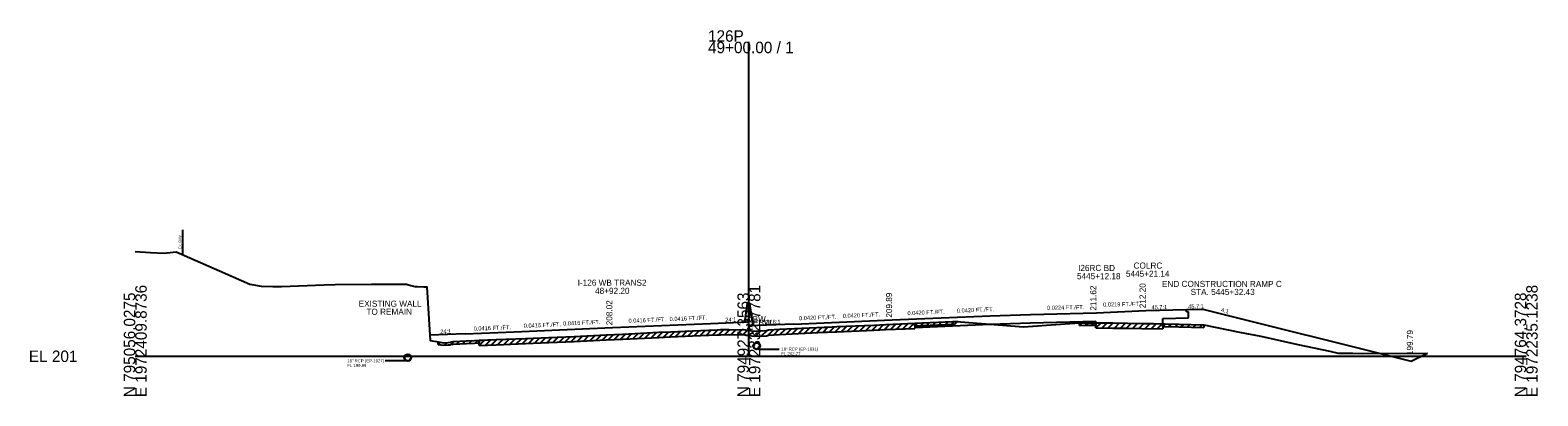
# Model space of a CAD drawing. Extents: x -161 to 1970889, y -4362 to 797231.
# Drawn here: x 1974.3 to 2342.8, y 1490.3 to 1579.8 of the extents above; entities that cross this region are included whole.
import ezdxf

# ---------------------------------------------------------------- set-up
doc = ezdxf.new("R2010")
doc.units = 0
for name, color, linetype in [('RD_GPK_XS_Cell', 7, 'Continuous'), ('RD_XS_Base', 7, 'Continuous'), ('RD_XS_EarthShd', 7, 'Continuous'), ('RD_XS_ExGround', 7, 'Continuous'), ('RD_XS_ExPaveRet', 7, 'Continuous'), ('RD_XS_ExRW', 7, 'Continuous'), ('RD_XS_MedBWall', 7, 'Continuous'), ('RD_XS_Misc_Line', 7, 'Continuous'), ('RD_XS_Pave', 7, 'Continuous'), ('RD_XS_PaveOvlay', 7, 'Continuous'), ('RD_XS_PaveShd', 7, 'Continuous'), ('RD_XS_Pipe', 7, 'Continuous'), ('RD_XS_TieSlope', 7, 'Continuous'), ('RD_XS_TX_Elev_EX', 7, 'Continuous'), ('RD_XS_TX_Elev_PR', 7, 'Continuous'), ('RD_XS_TX_Misc', 7, 'Continuous'), ('RD_XS_TX_MkPT', 7, 'Continuous'), ('RD_XS_TX_Notes', 7, 'Continuous'), ('RD_XS_TX_Profile', 7, 'Continuous'), ('RD_XS_TX_ShdSlope', 7, 'Continuous'), ('RD_XS_TX_Slope', 7, 'Continuous'), ('RD_XS_TX_Station', 7, 'Continuous')]:
    doc.layers.add(name, color=color, linetype=linetype)

msp = doc.modelspace()

# ---------------------------------------------------------------- linework, layer by layer
at = {"layer": 'RD_GPK_XS_Cell'}
for p, q in [((2150, 1500), (2150, 1576.99)), ((2000, 1500), (2150, 1500)), ((2150, 1500), (2340, 1500))]:
    msp.add_line(p, q, dxfattribs=at)
at = {"layer": 'RD_XS_Base'}
for p, q in [((2256.97, 1510.86), (2256.97, 1511.42)), ((2190.52, 1507.08), (2209, 1507.86)), ((2209, 1507.86), (2218.86, 1508.22)), ((2218.86, 1508.22), (2234.82, 1508.58)), ((2251.16, 1509.25), (2257.47, 1509.39)), ((2257.47, 1510.87), (2256.97, 1510.86)), ((2257.47, 1509.39), (2257.47, 1510.87))]:
    msp.add_line(p, q, dxfattribs=at)
at = {"layer": 'RD_XS_EarthShd'}
msp.add_line((2256.97, 1511.42), (2260.98, 1511.51), dxfattribs=at)
at = {"layer": 'RD_XS_ExGround'}
for points in [[(2000, 1525.66), (2003.69, 1525.44), (2007.1, 1525.22), (2007.77, 1525.34), (2009.96, 1525.6), (2023.96, 1519.48), (2028.04, 1517.66), (2028.52, 1517.56), (2030.78, 1517.2), (2033.6, 1517.11), (2034.53, 1517.05), (2035.75, 1517.1), (2046.16, 1517.52), (2048.89, 1517.58), (2057.72, 1517.68), (2062.21, 1517.65), (2063.99, 1517.63), (2065.81, 1517.62), (2066.29, 1517.62), (2067.38, 1517.35), (2068.3, 1517.08), (2068.94, 1517.07), (2070.5, 1517.01), (2071.26, 1517.01), (2072.05, 1503.87), (2072.6, 1503.77), (2073.66, 1503.61), (2075.35, 1503.33), (2076.51, 1503.4), (2077.09, 1503.43), (2077.33, 1503.55), (2077.58, 1503.54), (2077.69, 1503.61), (2080.99, 1503.76), (2082.93, 1503.86), (2088.21, 1504.07), (2095.41, 1504.35), (2101.05, 1504.6), (2107.31, 1504.88), (2115.1, 1505.24), (2119.21, 1505.42), (2128, 1505.88), (2130.8, 1506.01), (2136.22, 1506.25), (2142.25, 1506.51), (2143.08, 1506.53), (2145.02, 1506.57), (2145.3, 1506.48), (2148.31, 1506.56), (2148.62, 1506.56), (2150, 1506.35), (2151.37, 1506.14), (2154.33, 1506.28), (2154.79, 1506.44), (2157.46, 1506.6), (2168.38, 1507.12), (2169.11, 1507.16), (2171.47, 1507.25), (2180.55, 1507.64), (2183.46, 1507.77), (2192.44, 1508.18), (2199.88, 1508.52), (2200.52, 1508.55), (2201.13, 1508.48), (2201.68, 1508.46), (2217.11, 1507.24), (2226.17, 1507.87), (2230.8, 1508.2), (2232.54, 1508.2), (2234.75, 1508.21), (2238.99, 1508.17), (2242.54, 1508.13), (2246.04, 1508.06), (2251.77, 1507.93), (2255.12, 1507.84), (2261.2, 1507.68), (2269.93, 1505.91), (2275.15, 1504.96), (2284.18, 1502.9), (2291.97, 1501.23), (2294.06, 1500.79), (2294.54, 1500.79), (2297.6, 1500.76), (2300, 1500.72)], [(2300, 1500.72), (2315.83, 1500.78)]]:
    msp.add_lwpolyline(points, dxfattribs=at)
at = {"layer": 'RD_XS_ExPaveRet'}
for p, q in [((2190.52, 1508.09), (2190.52, 1506.84)), ((2190.52, 1507.47), (2190.52, 1508.09)), ((2190.52, 1507.47), (2192.44, 1507.56)), ((2192.44, 1507.56), (2199.88, 1507.9)), ((2199.88, 1507.9), (2200.52, 1507.92)), ((2200.52, 1508.55), (2200.52, 1507.92)), ((2230.8, 1507.57), (2230.8, 1508.2)), ((2230.8, 1507.57), (2232.54, 1507.58)), ((2232.54, 1507.58), (2234.75, 1507.59)), ((2234.75, 1507.59), (2234.82, 1507.59)), ((2234.82, 1506.96), (2234.82, 1508.21)), ((2234.82, 1508.21), (2234.82, 1507.59)), ((2251.16, 1507.94), (2251.16, 1506.69)), ((2251.16, 1507.32), (2251.16, 1507.94)), ((2251.16, 1507.32), (2251.77, 1507.31)), ((2251.77, 1507.31), (2255.12, 1507.21)), ((2261.2, 1507.68), (2261.2, 1507.06)), ((2084.08, 1502.66), (2084.08, 1503.91)), ((2084.08, 1503.91), (2084.08, 1503.28)), ((2101.05, 1503.35), (2107.31, 1503.63)), ((2107.31, 1503.63), (2115.1, 1503.99)), ((2115.1, 1503.99), (2119.21, 1504.17)), ((2119.21, 1504.17), (2128, 1504.63)), ((2128, 1504.63), (2130.8, 1504.76)), ((2130.8, 1504.76), (2136.22, 1505)), ((2136.22, 1505), (2142.25, 1505.26)), ((2142.25, 1505.26), (2143.08, 1505.28)), ((2143.08, 1505.28), (2145.02, 1505.32)), ((2145.02, 1505.32), (2145.3, 1505.23)), ((2145.3, 1505.23), (2148.31, 1505.31)), ((2148.31, 1505.31), (2148.62, 1505.31)), ((2148.62, 1505.31), (2150, 1505.1)), ((2150, 1505.1), (2151.37, 1504.89)), ((2151.37, 1504.89), (2154.33, 1505.03)), ((2154.33, 1505.03), (2154.79, 1505.19)), ((2154.79, 1505.19), (2157.46, 1505.35)), ((2157.46, 1505.35), (2168.38, 1505.87)), ((2168.38, 1505.87), (2169.11, 1505.91)), ((2169.11, 1505.91), (2171.47, 1506)), ((2171.47, 1506), (2180.55, 1506.39)), ((2180.55, 1506.39), (2183.46, 1506.52)), ((2183.46, 1506.52), (2190.52, 1506.84)), ((2234.82, 1506.96), (2238.99, 1506.92)), ((2238.99, 1506.92), (2242.54, 1506.88)), ((2242.54, 1506.88), (2246.04, 1506.81)), ((2246.04, 1506.81), (2251.16, 1506.69)), ((2255.12, 1507.21), (2261.2, 1507.06)), ((2074.08, 1502.91), (2074.08, 1503.54)), ((2074.08, 1502.91), (2075.35, 1502.71)), ((2075.35, 1502.71), (2076.51, 1502.77)), ((2076.51, 1502.77), (2077.09, 1502.81)), ((2077.09, 1502.81), (2077.33, 1502.93)), ((2077.33, 1502.93), (2077.58, 1502.91)), ((2077.58, 1502.91), (2077.69, 1502.99)), ((2077.69, 1502.99), (2080.99, 1503.14)), ((2080.99, 1503.14), (2082.93, 1503.24)), ((2082.93, 1503.24), (2084.08, 1503.28)), ((2084.08, 1502.66), (2088.21, 1502.82)), ((2088.21, 1502.82), (2095.41, 1503.1)), ((2095.41, 1503.1), (2101.05, 1503.35))]:
    msp.add_line(p, q, dxfattribs=at)
at = {"layer": 'RD_XS_ExRW'}
msp.add_line((2011.52, 1530.92), (2011.52, 1524.92), dxfattribs=at)
at = {"layer": 'RD_XS_MedBWall'}
for p, q in [((2149, 1508.37), (2149.67, 1512.91)), ((2150.19, 1512.91), (2149.67, 1512.91)), ((2151, 1507.46), (2150.19, 1512.91))]:
    msp.add_line(p, q, dxfattribs=at)
at = {"layer": 'RD_XS_Misc_Line'}
for p, q in [((2172.59, 1506.05), (2173.9, 1507.36)), ((2174.09, 1506.11), (2175.4, 1507.42)), ((2175.59, 1506.18), (2176.9, 1507.48)), ((2177.09, 1506.24), (2178.4, 1507.55)), ((2178.59, 1506.3), (2179.9, 1507.61)), ((2180.09, 1506.37), (2181.4, 1507.68)), ((2181.59, 1506.43), (2182.9, 1507.74)), ((2183.09, 1506.5), (2184.4, 1507.81)), ((2184.59, 1506.57), (2185.9, 1507.88)), ((2186.09, 1506.64), (2187.4, 1507.95)), ((2187.59, 1506.71), (2188.9, 1508.02)), ((2189.09, 1506.78), (2190.4, 1508.09)), ((2190.52, 1507.47), (2191.17, 1508.12)), ((2192.02, 1507.54), (2192.67, 1508.19)), ((2193.52, 1507.61), (2194.17, 1508.26)), ((2195.02, 1507.67), (2195.67, 1508.33)), ((2196.52, 1507.74), (2197.17, 1508.4)), ((2198.02, 1507.81), (2198.68, 1508.47)), ((2199.52, 1507.88), (2200.17, 1508.53)), ((2230.8, 1507.57), (2231.42, 1508.2)), ((2232.3, 1507.58), (2232.92, 1508.2)), ((2233.8, 1507.58), (2234.43, 1508.21)), ((2234.82, 1506.96), (2236.06, 1508.2)), ((2236.32, 1506.95), (2237.56, 1508.19)), ((2237.82, 1506.93), (2239.06, 1508.17)), ((2239.32, 1506.92), (2240.56, 1508.15)), ((2240.82, 1506.9), (2242.06, 1508.14)), ((2242.32, 1506.89), (2243.55, 1508.11)), ((2243.82, 1506.86), (2245.04, 1508.08)), ((2245.32, 1506.82), (2246.54, 1508.05)), ((2246.82, 1506.79), (2248.04, 1508.01)), ((2248.32, 1506.76), (2249.54, 1507.98)), ((2249.82, 1506.72), (2251.04, 1507.95)), ((2251.16, 1507.32), (2251.77, 1507.93)), ((2252.66, 1507.28), (2253.27, 1507.89)), ((2254.16, 1507.24), (2254.77, 1507.85)), ((2255.66, 1507.2), (2256.27, 1507.81)), ((2257.16, 1507.16), (2257.77, 1507.77)), ((2258.66, 1507.12), (2259.27, 1507.73)), ((2260.16, 1507.08), (2260.77, 1507.69)), ((2077.08, 1502.81), (2077.9, 1503.62)), ((2078.58, 1503.03), (2079.24, 1503.68)), ((2080.08, 1503.1), (2080.74, 1503.75)), ((2081.58, 1503.17), (2082.24, 1503.83)), ((2083.08, 1503.25), (2083.73, 1503.9)), ((2084.08, 1502.66), (2085.38, 1503.96)), ((2085.58, 1502.72), (2086.88, 1504.02)), ((2087.08, 1502.78), (2088.38, 1504.08)), ((2088.58, 1502.84), (2089.88, 1504.14)), ((2090.08, 1502.89), (2091.38, 1504.19)), ((2091.58, 1502.95), (2092.88, 1504.25)), ((2093.08, 1503.01), (2094.38, 1504.31)), ((2094.58, 1503.07), (2095.89, 1504.37)), ((2096.08, 1503.13), (2097.39, 1504.44)), ((2097.58, 1503.2), (2098.89, 1504.5)), ((2099.08, 1503.26), (2100.39, 1504.57)), ((2100.58, 1503.33), (2101.89, 1504.64)), ((2102.08, 1503.4), (2103.39, 1504.71)), ((2103.58, 1503.46), (2104.89, 1504.77)), ((2105.08, 1503.53), (2106.39, 1504.84)), ((2106.58, 1503.6), (2107.89, 1504.91)), ((2108.08, 1503.67), (2109.39, 1504.98)), ((2109.58, 1503.74), (2110.9, 1505.05)), ((2111.09, 1503.81), (2112.4, 1505.12)), ((2112.59, 1503.87), (2113.9, 1505.18)), ((2114.09, 1503.94), (2115.4, 1505.25)), ((2115.59, 1504.01), (2116.89, 1505.32)), ((2117.09, 1504.08), (2118.4, 1505.39)), ((2118.59, 1504.15), (2119.9, 1505.46)), ((2120.09, 1504.22), (2121.4, 1505.54)), ((2121.59, 1504.3), (2122.9, 1505.61)), ((2123.09, 1504.37), (2124.4, 1505.69)), ((2124.59, 1504.45), (2125.9, 1505.77)), ((2126.09, 1504.53), (2127.4, 1505.84)), ((2127.59, 1504.6), (2128.9, 1505.92)), ((2129.09, 1504.68), (2130.4, 1505.99)), ((2130.59, 1504.75), (2131.9, 1506.06)), ((2132.09, 1504.82), (2133.39, 1506.12)), ((2133.59, 1504.88), (2134.9, 1506.19)), ((2135.09, 1504.95), (2136.4, 1506.26)), ((2136.59, 1505.01), (2137.89, 1506.32)), ((2138.09, 1505.08), (2139.39, 1506.38)), ((2139.59, 1505.14), (2140.89, 1506.45)), ((2141.09, 1505.21), (2142.39, 1506.51)), ((2142.59, 1505.27), (2143.87, 1506.55)), ((2144.09, 1505.3), (2145.27, 1506.49)), ((2145.59, 1505.24), (2146.87, 1506.52)), ((2147.09, 1505.28), (2148.37, 1506.56)), ((2148.59, 1505.31), (2149.68, 1506.4)), ((2150.09, 1505.09), (2151.17, 1506.17)), ((2151.59, 1504.9), (2152.9, 1506.21)), ((2153.09, 1504.97), (2154.43, 1506.32)), ((2154.59, 1505.12), (2155.98, 1506.51)), ((2156.09, 1505.27), (2157.42, 1506.6)), ((2157.59, 1505.36), (2158.9, 1506.67)), ((2159.09, 1505.43), (2160.4, 1506.74)), ((2160.59, 1505.5), (2161.9, 1506.82)), ((2162.09, 1505.57), (2163.4, 1506.89)), ((2163.59, 1505.65), (2164.9, 1506.96)), ((2165.09, 1505.72), (2166.4, 1507.03)), ((2166.59, 1505.79), (2167.9, 1507.1)), ((2168.09, 1505.86), (2169.4, 1507.17)), ((2169.59, 1505.93), (2170.9, 1507.23)), ((2171.09, 1505.99), (2172.4, 1507.29)), ((2074.08, 1502.91), (2074.62, 1503.45)), ((2075.58, 1502.72), (2076.24, 1503.38))]:
    msp.add_line(p, q, dxfattribs=at)
at = {"layer": 'RD_XS_Pave'}
for p, q in [((2234.92, 1510.62), (2246.98, 1511.2)), ((2116.63, 1507.02), (2140.63, 1508.02)), ((2161, 1507.88), (2185, 1508.89)), ((2185, 1508.89), (2209, 1509.9)), ((2218.86, 1510.26), (2234.92, 1510.62)), ((2080.63, 1505.52), (2092.63, 1506.02)), ((2092.63, 1506.02), (2116.63, 1507.02))]:
    msp.add_line(p, q, dxfattribs=at)
at = {"layer": 'RD_XS_PaveOvlay'}
for p, q in [((2171.47, 1507.25), (2180.55, 1507.64)), ((2180.55, 1507.64), (2183.46, 1507.77)), ((2183.46, 1507.77), (2190.52, 1508.09)), ((2190.52, 1508.09), (2190.52, 1507.08)), ((2234.82, 1508.21), (2234.82, 1508.58)), ((2234.82, 1508.21), (2238.99, 1508.17)), ((2238.99, 1508.17), (2242.54, 1508.13)), ((2242.54, 1508.13), (2246.04, 1508.06)), ((2246.04, 1508.06), (2248.9, 1507.99)), ((2248.9, 1507.99), (2251.04, 1507.95)), ((2251.04, 1507.95), (2251.16, 1507.94)), ((2251.16, 1507.94), (2251.16, 1509.25)), ((2084.08, 1503.91), (2088.21, 1504.07)), ((2088.21, 1504.07), (2095.41, 1504.35)), ((2095.41, 1504.35), (2101.05, 1504.6)), ((2101.05, 1504.6), (2107.31, 1504.88)), ((2107.31, 1504.88), (2115.1, 1505.24)), ((2115.1, 1505.24), (2119.21, 1505.42)), ((2119.21, 1505.42), (2128, 1505.88)), ((2128, 1505.88), (2130.8, 1506.01)), ((2130.8, 1506.01), (2136.22, 1506.25)), ((2136.22, 1506.25), (2142.25, 1506.51)), ((2142.25, 1506.51), (2143.08, 1506.53)), ((2143.08, 1506.53), (2145.02, 1506.57)), ((2145.02, 1506.57), (2145.3, 1506.48)), ((2145.3, 1506.48), (2148.31, 1506.56)), ((2148.31, 1506.56), (2148.62, 1506.56)), ((2148.62, 1506.56), (2150, 1506.35)), ((2150, 1506.35), (2151.37, 1506.14)), ((2151.37, 1506.14), (2154.33, 1506.28)), ((2154.33, 1506.28), (2154.79, 1506.44)), ((2154.79, 1506.44), (2157.46, 1506.6)), ((2157.46, 1506.6), (2168.38, 1507.12)), ((2168.38, 1507.12), (2169.11, 1507.16)), ((2169.11, 1507.16), (2171.47, 1507.25))]:
    msp.add_line(p, q, dxfattribs=at)
msp.add_lwpolyline([(2071.98, 1505.16), (2072.05, 1503.87), (2072.6, 1503.77), (2073.66, 1503.61), (2075.35, 1503.33), (2076.51, 1503.4), (2077.09, 1503.43), (2077.33, 1503.55), (2077.58, 1503.54), (2077.69, 1503.61), (2080.99, 1503.76), (2082.93, 1503.86), (2084.08, 1503.91)], dxfattribs=at)
at = {"layer": 'RD_XS_PaveShd'}
for p, q in [((2246.98, 1511.2), (2256.97, 1511.42)), ((2140.63, 1508.02), (2150, 1508.41)), ((2150, 1507.42), (2150, 1508.41)), ((2161, 1507.88), (2150, 1507.42)), ((2209, 1509.9), (2218.86, 1510.26)), ((2080.63, 1505.52), (2071.98, 1505.16))]:
    msp.add_line(p, q, dxfattribs=at)
at = {"layer": 'RD_XS_Pipe'}
for p, q in [((2152.42, 1501.77), (2157.42, 1501.77)), ((2066.11, 1498.89), (2061.11, 1498.89))]:
    msp.add_line(p, q, dxfattribs=at)
for centre, radius in [((2066.61, 1499.64), 0.85), ((2066.61, 1499.64), 0.75), ((2151.92, 1502.52), 0.85), ((2151.92, 1502.52), 0.75)]:
    msp.add_circle(centre, radius, dxfattribs=at)
at = {"layer": 'RD_XS_TieSlope'}
for p, q in [((2260.98, 1511.51), (2311.86, 1498.79)), ((2311.86, 1498.79), (2315.83, 1500.78))]:
    msp.add_line(p, q, dxfattribs=at)

# ---------------------------------------------------------------- texts
at = {"layer": 'RD_GPK_XS_Cell'}
for s, p in [('126P', (2140, 1576.99)), ('49+00.00 / 1', (2140, 1574.19)), ('EL 201', (1974, 1498.6))]:
    msp.add_text(s, height=2.8, dxfattribs=at).set_placement(p)
for s, p in [('N 795056.0275', (2000, 1490)), ('E 1972409.8736', (2002.8, 1490)), ('N 794927.3563', (2150, 1490)), ('E 1972332.7781', (2152.8, 1490)), ('N 794764.3728', (2340, 1490)), ('E 1972235.1238', (2342.8, 1490))]:
    msp.add_text(s, height=2.8, rotation=90, dxfattribs=at).set_placement(p)
at = {"layer": 'RD_XS_ExRW'}
msp.add_text('Ex. R/W ', height=0.65, rotation=90, dxfattribs=at).set_placement((2011.27, 1526.3))
at = {"layer": 'RD_XS_Pipe'}
for s, p in [('18" RCP (EP-1931)', (2157.92, 1501.39)), ('FL 202.77', (2157.92, 1500.27)), ('18" RCP (EP-1927)', (2051.82, 1498.51)), ('FL 199.89', (2051.82, 1497.39))]:
    msp.add_text(s, height=0.75, dxfattribs=at).set_placement(p)
at = {"layer": 'RD_XS_TX_Elev_EX'}
msp.add_text('207.35', height=1, rotation=90, dxfattribs=at).set_placement((2151, 1506.35))
at = {"layer": 'RD_XS_TX_Elev_PR'}
for s, p in [(' 209.89', (2185, 1508.89)), (' 211.62', (2234.92, 1510.62)), (' 212.20', (2246.98, 1511.2)), (' 208.02', (2116.63, 1507.02))]:
    msp.add_text(s, height=1.5, rotation=90, dxfattribs=at).set_placement(p)
at = {"layer": 'RD_XS_TX_Misc'}
msp.add_text('199.79', height=1.5, rotation=90, dxfattribs=at).set_placement((2312.32, 1500.29))
at = {"layer": 'RD_XS_TX_MkPT'}
for s, p in [('WBW', (2149, 1508.37)), ('EBW', (2151, 1507.46))]:
    msp.add_text(s, height=1.5, dxfattribs=at).set_placement(p)
at = {"layer": 'RD_XS_TX_Notes'}
for s, p in [('END CONSTRUCTION RAMP C', (2250.95, 1516.96)), ('STA. 5445+32.43', (2257.97, 1515)), ('EXISTING WALL', (2054.61, 1512.12)), ('TO REMAIN', (2056.5, 1510.15))]:
    msp.add_text(s, height=1.5, dxfattribs=at).set_placement(p)
at = {"layer": 'RD_XS_TX_Profile'}
for s, rotation, p in [('24:1', 2.3827, (2144.25, 1508.42)), ('23.8:1', 2.405, (2153.91, 1507.83)), ('24:1', 2.3821, (2074.56, 1505.52))]:
    msp.add_text(s, height=1, rotation=rotation, dxfattribs=at).set_placement(p)
at = {"layer": 'RD_XS_TX_ShdSlope'}
msp.add_text('45.7:1', height=1, rotation=1.2522, dxfattribs=at).set_placement((2257.39, 1511.68))
at = {"layer": 'RD_XS_TX_Slope'}
for s, rotation, p in [('0.0420 FT./FT.', 2.405, (2188.77, 1510.05)), ('0.0420 FT./FT.', 2.405, (2200.85, 1510.65)), ('0.0224 FT./FT.', 1.2827, (2222.86, 1511.35)), ('0.0219 FT./FT.', 1.2524, (2236.59, 1512.15)), ('45.7:1', 1.2522, (2248.41, 1511.48)), ('4:1', 344.1175, (2265.32, 1510.96)), ('0.0416 FT./FT.', 2.3824, (2082.73, 1506.25)), ('0.0416 FT./FT.', 2.3821, (2094.98, 1506.96)), ('0.0416 FT./FT.', 2.3821, (2104.59, 1507.52)), ('0.0416 FT./FT.', 2.3827, (2120.59, 1508.18)), ('0.0416 FT./FT.', 2.3821, (2130.63, 1508.6)), ('0.0420 FT./FT.', 2.405, (2162.28, 1508.81)), ('0.0420 FT./FT.', 2.405, (2172.96, 1509.38))]:
    msp.add_text(s, height=1, rotation=rotation, dxfattribs=at).set_placement(p)
at = {"layer": 'RD_XS_TX_Station'}
for s, p in [('I26RC BD', (2230.46, 1520.87)), ('COLRC', (2244.02, 1521.45)), ('I-126 WB TRANS2', (2108.14, 1517.27)), ('5445+12.18', (2230.18, 1518.87)), ('5445+21.14', (2242.15, 1519.45)), ('48+92.20', (2112.39, 1515.27))]:
    msp.add_text(s, height=1.5, dxfattribs=at).set_placement(p)

doc.saveas('drawing.dxf')
